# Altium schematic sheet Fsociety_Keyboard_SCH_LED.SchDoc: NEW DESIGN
size A1; CompanyName: Rena Electronica; Engineer: IK; Organization: Rena Electronica; Address1: de Ambachten 12; Address2: 4881 XZ; Address3: Zundert; Address4: the Netherlands; DocumentNumber: 05.xxx; Revision: 0.10; Customer: Klantnaam; PageSetup: Record=PageOptions¦CenterHorizontal=True¦CenterVertical=True¦PrintScale=0.52¦XCorrection=1.00¦YCorrection=1.00¦PrintKind=0¦BorderSize=5000000¦LeftOffset=0¦BottomOffset=0¦Orientation=2¦PaperLength=1000¦PaperWidth=1000¦Scale=100¦PaperSource=7¦PrintQuality=-3¦MediaType=1¦DitherType=10¦PrintScaleMode=1¦PaperKind=A3¦PaperIndex=8
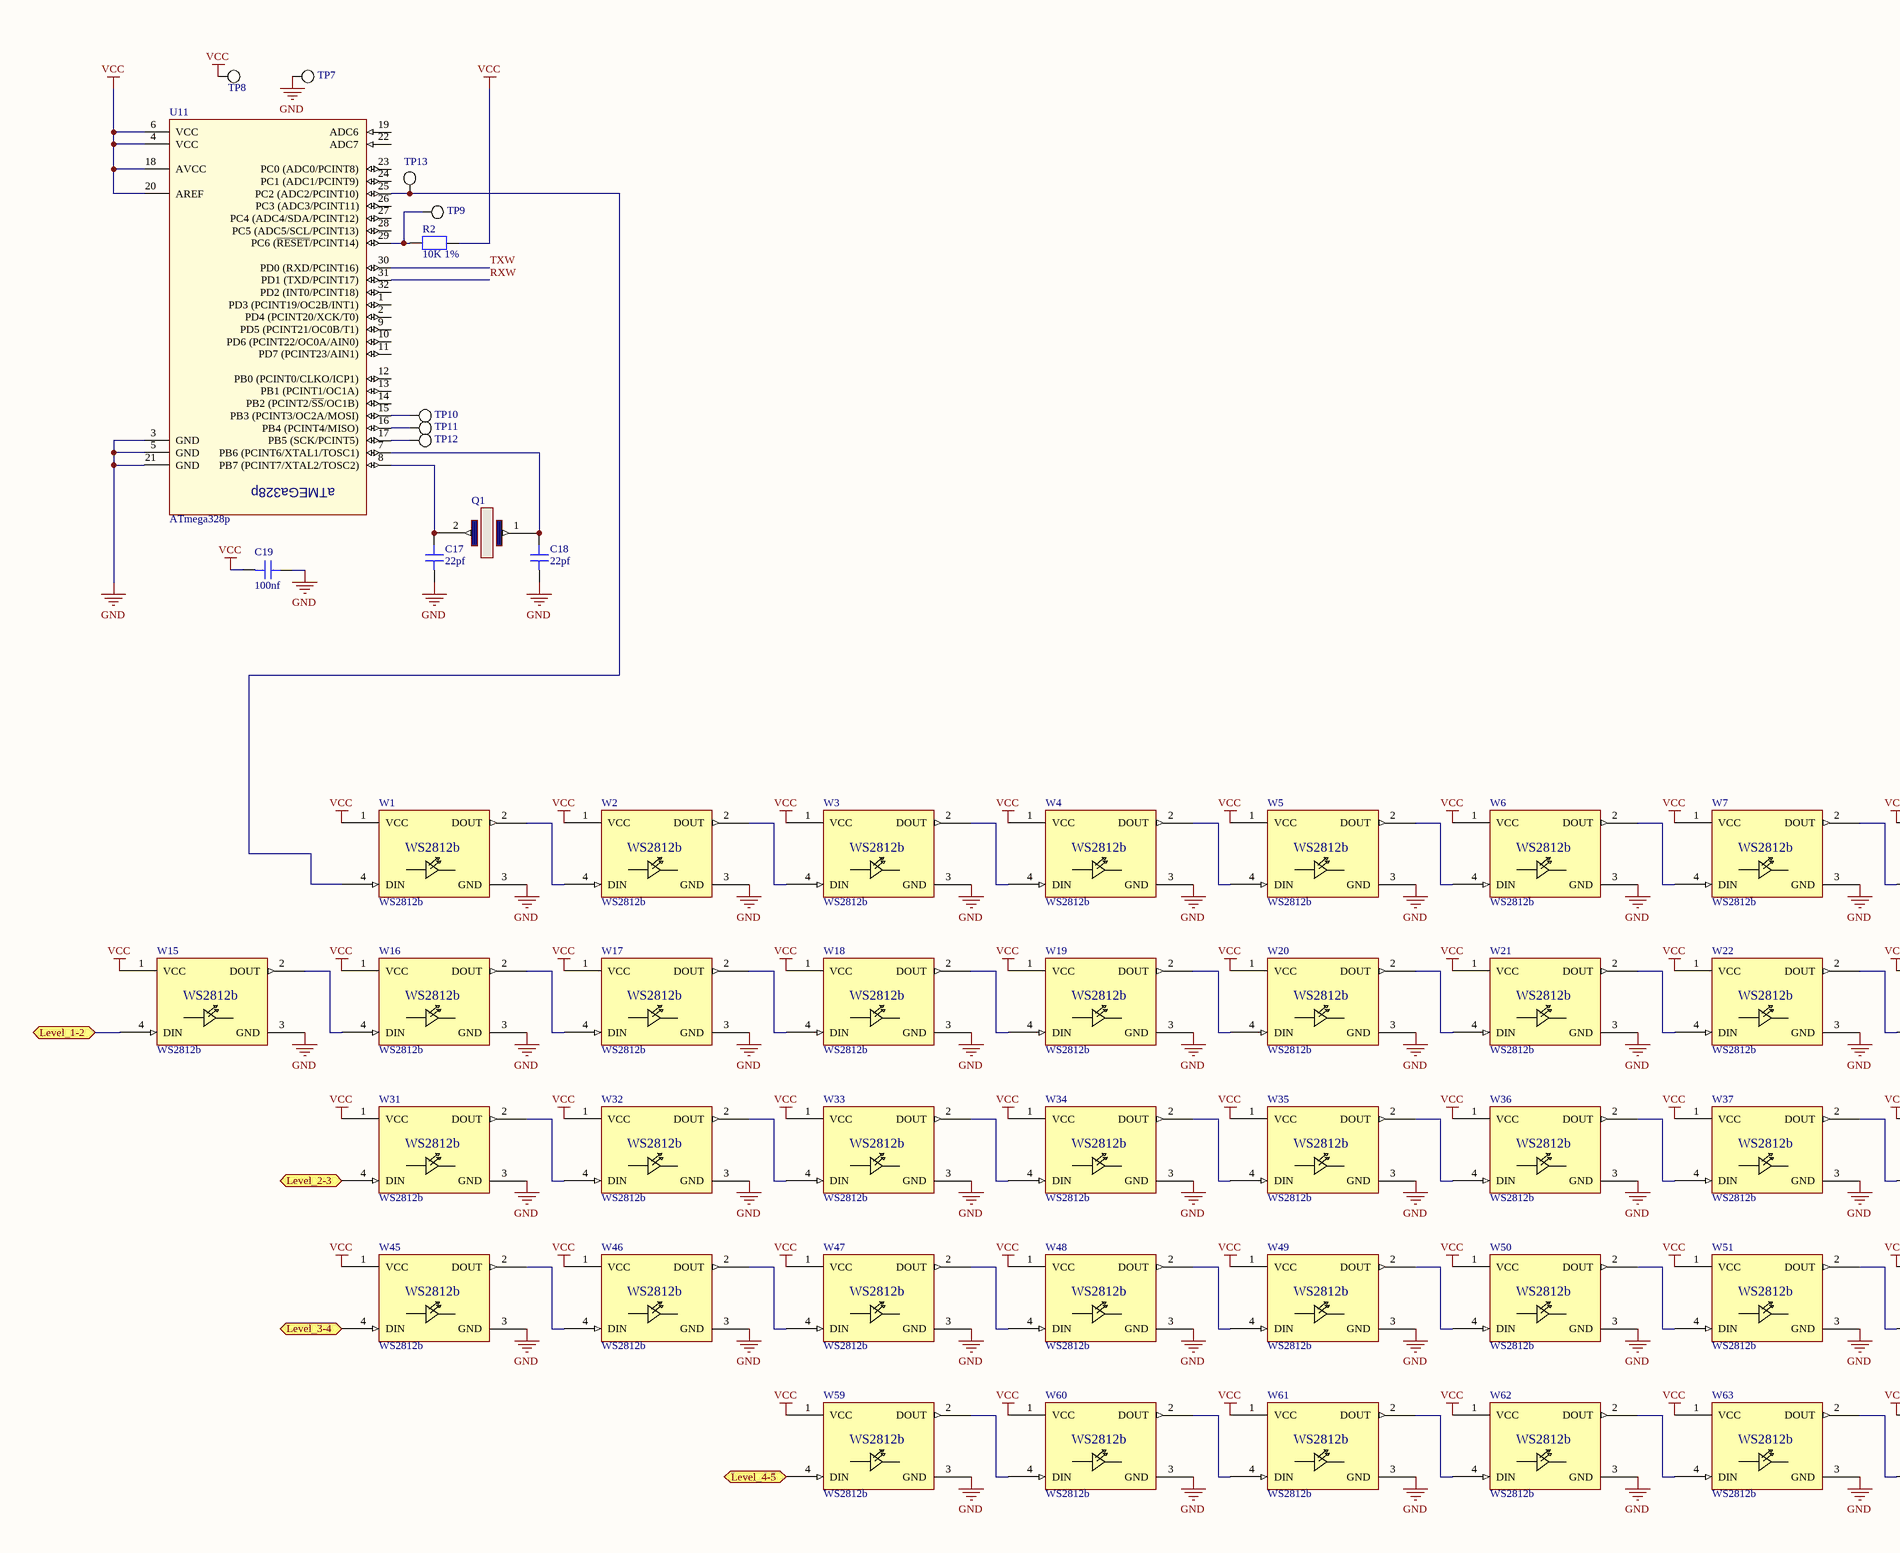
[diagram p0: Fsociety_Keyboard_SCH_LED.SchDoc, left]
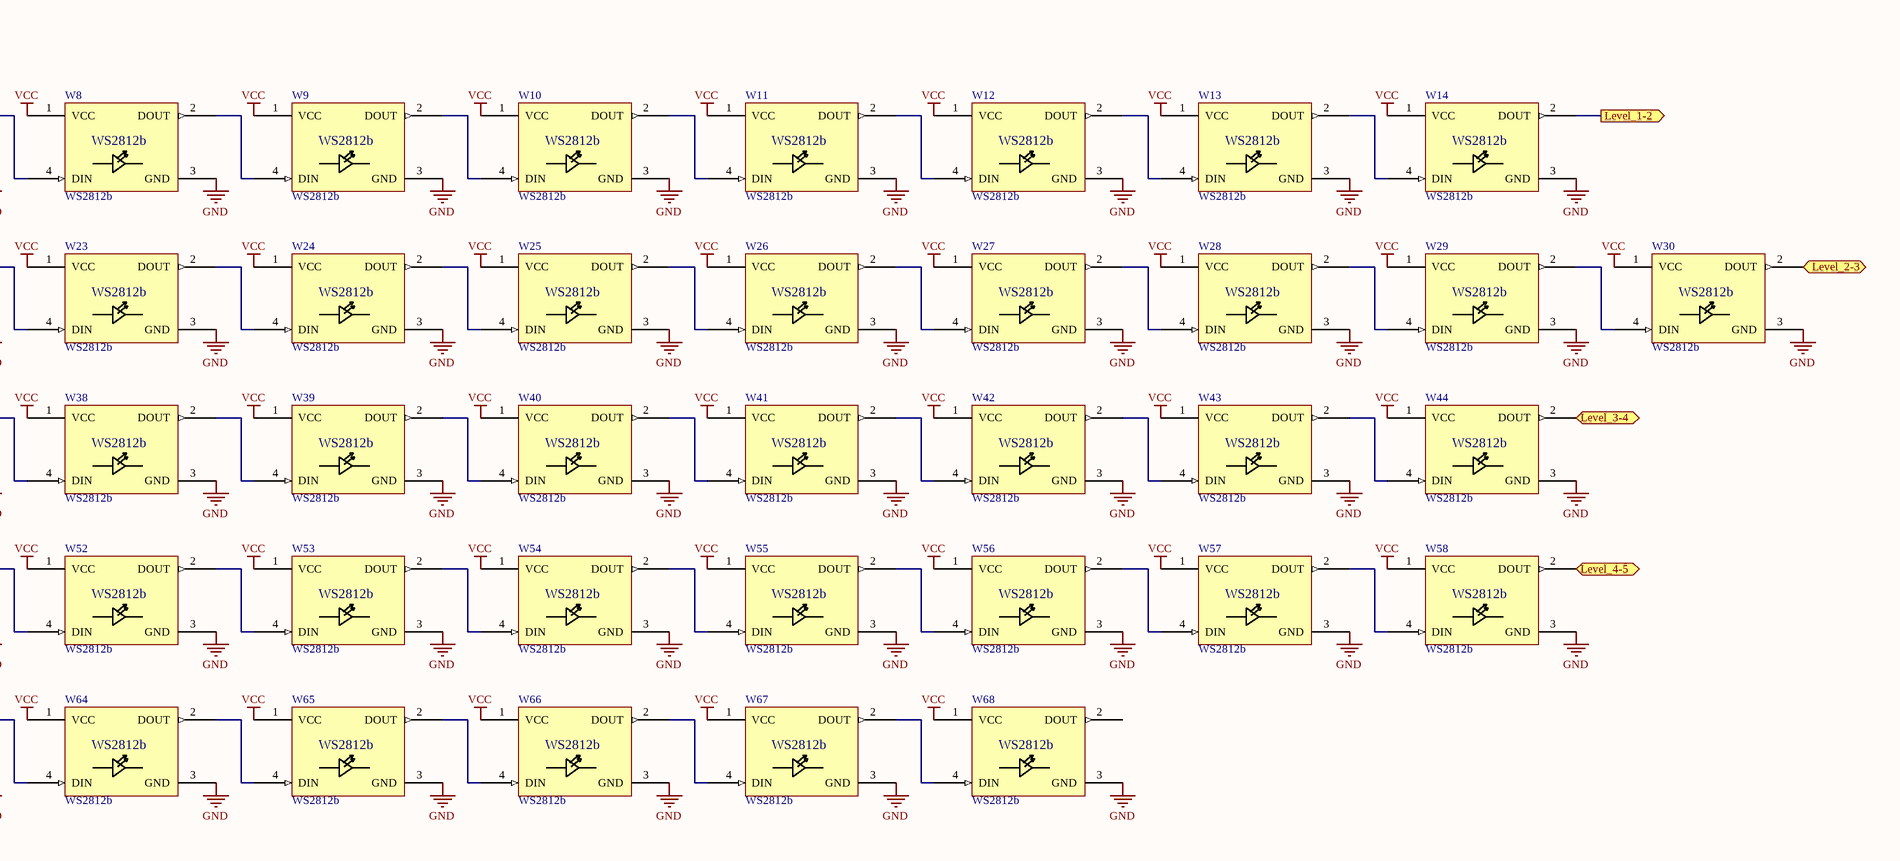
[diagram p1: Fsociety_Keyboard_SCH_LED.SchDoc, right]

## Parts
C17  22pf  [CAPC1608X08_NR]
C18  22pf  [CAPC1608X08_NR]
C19  100nf  [CAPC1608X08_NR]
Q1  Crystal_txc_sumasta  [Crystal_txc_sumasta]  (value not drawn)
R2  10K 1%  [RESC1608X06_NR]
TP7  TP  [TESTPAD-2MM]  (value not drawn)  (no BOM)
TP8  TP  [TESTPAD-2MM]  (value not drawn)  (no BOM)
TP9  TP  [TESTPAD-2MM]  (value not drawn)  (no BOM)
TP10  TP  [TESTPAD-2MM]  (value not drawn)  (no BOM)
TP11  TP  [TESTPAD-2MM]  (value not drawn)  (no BOM)
TP12  TP  [TESTPAD-2MM]  (value not drawn)  (no BOM)
TP13  TP  [TESTPAD-2MM]  (value not drawn)  (no BOM)
U11  ATmega328p  [TQFP32]
W1  WS2812b  [DIOC500500X250_NR]
W2  WS2812b  [DIOC500500X250_NR]
W3  WS2812b  [DIOC500500X250_NR]
W4  WS2812b  [DIOC500500X250_NR]
W5  WS2812b  [DIOC500500X250_NR]
W6  WS2812b  [DIOC500500X250_NR]
W7  WS2812b  [DIOC500500X250_NR]
W8  WS2812b  [DIOC500500X250_NR]
W9  WS2812b  [DIOC500500X250_NR]
W10  WS2812b  [DIOC500500X250_NR]
W11  WS2812b  [DIOC500500X250_NR]
W12  WS2812b  [DIOC500500X250_NR]
W13  WS2812b  [DIOC500500X250_NR]
W14  WS2812b  [DIOC500500X250_NR]
W15  WS2812b  [DIOC500500X250_NR]
W16  WS2812b  [DIOC500500X250_NR]
W17  WS2812b  [DIOC500500X250_NR]
W18  WS2812b  [DIOC500500X250_NR]
W19  WS2812b  [DIOC500500X250_NR]
W20  WS2812b  [DIOC500500X250_NR]
W21  WS2812b  [DIOC500500X250_NR]
W22  WS2812b  [DIOC500500X250_NR]
W23  WS2812b  [DIOC500500X250_NR]
W24  WS2812b  [DIOC500500X250_NR]
W25  WS2812b  [DIOC500500X250_NR]
W26  WS2812b  [DIOC500500X250_NR]
W27  WS2812b  [DIOC500500X250_NR]
W28  WS2812b  [DIOC500500X250_NR]
W29  WS2812b  [DIOC500500X250_NR]
W30  WS2812b  [DIOC500500X250_NR]
W31  WS2812b  [DIOC500500X250_NR]
W32  WS2812b  [DIOC500500X250_NR]
W33  WS2812b  [DIOC500500X250_NR]
W34  WS2812b  [DIOC500500X250_NR]
W35  WS2812b  [DIOC500500X250_NR]
W36  WS2812b  [DIOC500500X250_NR]
W37  WS2812b  [DIOC500500X250_NR]
W38  WS2812b  [DIOC500500X250_NR]
W39  WS2812b  [DIOC500500X250_NR]
W40  WS2812b  [DIOC500500X250_NR]
W41  WS2812b  [DIOC500500X250_NR]
W42  WS2812b  [DIOC500500X250_NR]
W43  WS2812b  [DIOC500500X250_NR]
W44  WS2812b  [DIOC500500X250_NR]
W45  WS2812b  [DIOC500500X250_NR]
W46  WS2812b  [DIOC500500X250_NR]
W47  WS2812b  [DIOC500500X250_NR]
W48  WS2812b  [DIOC500500X250_NR]
W49  WS2812b  [DIOC500500X250_NR]
W50  WS2812b  [DIOC500500X250_NR]
W51  WS2812b  [DIOC500500X250_NR]
W52  WS2812b  [DIOC500500X250_NR]
W53  WS2812b  [DIOC500500X250_NR]
W54  WS2812b  [DIOC500500X250_NR]
W55  WS2812b  [DIOC500500X250_NR]
W56  WS2812b  [DIOC500500X250_NR]
W57  WS2812b  [DIOC500500X250_NR]
W58  WS2812b  [DIOC500500X250_NR]
W59  WS2812b  [DIOC500500X250_NR]
W60  WS2812b  [DIOC500500X250_NR]
W61  WS2812b  [DIOC500500X250_NR]
W62  WS2812b  [DIOC500500X250_NR]
W63  WS2812b  [DIOC500500X250_NR]
W64  WS2812b  [DIOC500500X250_NR]
W65  WS2812b  [DIOC500500X250_NR]
W66  WS2812b  [DIOC500500X250_NR]
W67  WS2812b  [DIOC500500X250_NR]
W68  WS2812b  [DIOC500500X250_NR]

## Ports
Level_1-2, Level_1-2 (out), Level_2-3, Level_3-4, Level_4-5

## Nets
GND: C17.1 C18.1 C19.2 TP7.1 U11.3(GND) U11.5(GND) U11.21(GND) W1.3(GND) W2.3(GND) W3.3(GND) W4.3(GND) W5.3(GND) W6.3(GND) W7.3(GND) W8.3(GND) W9.3(GND) W10.3(GND) W11.3(GND) W12.3(GND) W13.3(GND) W14.3(GND) W15.3(GND) W16.3(GND) W17.3(GND) W18.3(GND) W19.3(GND) W20.3(GND) W21.3(GND) W22.3(GND) W23.3(GND) W24.3(GND) W25.3(GND) W26.3(GND) W27.3(GND) W28.3(GND) W29.3(GND) W30.3(GND) W31.3(GND) W32.3(GND) W33.3(GND) W34.3(GND) W35.3(GND) W36.3(GND) W37.3(GND) W38.3(GND) W39.3(GND) W40.3(GND) W41.3(GND) W42.3(GND) W43.3(GND) W44.3(GND) W45.3(GND) W46.3(GND) W47.3(GND) W48.3(GND) W49.3(GND) W50.3(GND) W51.3(GND) W52.3(GND) W53.3(GND) W54.3(GND) W55.3(GND) W56.3(GND) W57.3(GND) W58.3(GND) W59.3(GND) W60.3(GND) W61.3(GND) W62.3(GND) W63.3(GND) W64.3(GND) W65.3(GND) W66.3(GND) W67.3(GND) W68.3(GND)
VCC: C19.1 R2.1 TP8.1 U11.4(VCC) U11.6(VCC) U11.18(AVCC) U11.20(AREF) W1.1(VCC) W2.1(VCC) W3.1(VCC) W4.1(VCC) W5.1(VCC) W6.1(VCC) W7.1(VCC) W8.1(VCC) W9.1(VCC) W10.1(VCC) W11.1(VCC) W12.1(VCC) W13.1(VCC) W14.1(VCC) W15.1(VCC) W16.1(VCC) W17.1(VCC) W18.1(VCC) W19.1(VCC) W20.1(VCC) W21.1(VCC) W22.1(VCC) W23.1(VCC) W24.1(VCC) W25.1(VCC) W26.1(VCC) W27.1(VCC) W28.1(VCC) W29.1(VCC) W30.1(VCC) W31.1(VCC) W32.1(VCC) W33.1(VCC) W34.1(VCC) W35.1(VCC) W36.1(VCC) W37.1(VCC) W38.1(VCC) W39.1(VCC) W40.1(VCC) W41.1(VCC) W42.1(VCC) W43.1(VCC) W44.1(VCC) W45.1(VCC) W46.1(VCC) W47.1(VCC) W48.1(VCC) W49.1(VCC) W50.1(VCC) W51.1(VCC) W52.1(VCC) W53.1(VCC) W54.1(VCC) W55.1(VCC) W56.1(VCC) W57.1(VCC) W58.1(VCC) W59.1(VCC) W60.1(VCC) W61.1(VCC) W62.1(VCC) W63.1(VCC) W64.1(VCC) W65.1(VCC) W66.1(VCC) W67.1(VCC) W68.1(VCC)
Level_1-2: W14.2(DOUT) W15.4(DIN) ; port Level_1-2
Level_2-3: W30.2(DOUT) W31.4(DIN) ; port Level_2-3
Level_3-4: W44.2(DOUT) W45.4(DIN) ; port Level_3-4
Level_4-5: W58.2(DOUT) W59.4(DIN) ; port Level_4-5
RXW: U11.31(PD1_(TXD/PCINT17))
TXW: U11.30(PD0_(RXD/PCINT16))
NetC17_2: C17.2 Q1.2 U11.8(PB7_(PCINT7/XTAL2/TOSC2))
NetC18_2: C18.2 Q1.1 U11.7(PB6_(PCINT6/XTAL1/TOSC1))
NetR2_2: R2.2 TP9.1 U11.29(PC6_(~{RESET}/PCINT14))
NetTP10_1: TP10.1 U11.15(PB3_(PCINT3/OC2A/MOSI))
NetTP11_1: TP11.1 U11.16(PB4_(PCINT4/MISO))
NetTP12_1: TP12.1 U11.17(PB5_(SCK/PCINT5))
NetTP13_1: TP13.1 U11.25(PC2_(ADC2/PCINT10)) W1.4(DIN)
NetW1_2: W1.2(DOUT) W2.4(DIN)
NetW2_2: W2.2(DOUT) W3.4(DIN)
NetW3_2: W3.2(DOUT) W4.4(DIN)
NetW4_2: W4.2(DOUT) W5.4(DIN)
NetW5_2: W5.2(DOUT) W6.4(DIN)
NetW6_2: W6.2(DOUT) W7.4(DIN)
NetW7_2: W7.2(DOUT) W8.4(DIN)
NetW8_2: W8.2(DOUT) W9.4(DIN)
NetW9_2: W9.2(DOUT) W10.4(DIN)
NetW10_2: W10.2(DOUT) W11.4(DIN)
NetW11_2: W11.2(DOUT) W12.4(DIN)
NetW12_2: W12.2(DOUT) W13.4(DIN)
NetW13_2: W13.2(DOUT) W14.4(DIN)
NetW15_2: W15.2(DOUT) W16.4(DIN)
NetW16_2: W16.2(DOUT) W17.4(DIN)
NetW17_2: W17.2(DOUT) W18.4(DIN)
NetW18_2: W18.2(DOUT) W19.4(DIN)
NetW19_2: W19.2(DOUT) W20.4(DIN)
NetW20_2: W20.2(DOUT) W21.4(DIN)
NetW21_2: W21.2(DOUT) W22.4(DIN)
NetW22_2: W22.2(DOUT) W23.4(DIN)
NetW23_2: W23.2(DOUT) W24.4(DIN)
NetW24_2: W24.2(DOUT) W25.4(DIN)
NetW25_2: W25.2(DOUT) W26.4(DIN)
NetW26_2: W26.2(DOUT) W27.4(DIN)
NetW27_2: W27.2(DOUT) W28.4(DIN)
NetW28_2: W28.2(DOUT) W29.4(DIN)
NetW29_2: W29.2(DOUT) W30.4(DIN)
NetW31_2: W31.2(DOUT) W32.4(DIN)
NetW32_2: W32.2(DOUT) W33.4(DIN)
NetW33_2: W33.2(DOUT) W34.4(DIN)
NetW34_2: W34.2(DOUT) W35.4(DIN)
NetW35_2: W35.2(DOUT) W36.4(DIN)
NetW36_2: W36.2(DOUT) W37.4(DIN)
NetW37_2: W37.2(DOUT) W38.4(DIN)
NetW38_2: W38.2(DOUT) W39.4(DIN)
NetW39_2: W39.2(DOUT) W40.4(DIN)
NetW40_2: W40.2(DOUT) W41.4(DIN)
NetW41_2: W41.2(DOUT) W42.4(DIN)
NetW42_2: W42.2(DOUT) W43.4(DIN)
NetW43_2: W43.2(DOUT) W44.4(DIN)
NetW45_2: W45.2(DOUT) W46.4(DIN)
NetW46_2: W46.2(DOUT) W47.4(DIN)
NetW47_2: W47.2(DOUT) W48.4(DIN)
NetW48_2: W48.2(DOUT) W49.4(DIN)
NetW49_2: W49.2(DOUT) W50.4(DIN)
NetW50_2: W50.2(DOUT) W51.4(DIN)
NetW51_2: W51.2(DOUT) W52.4(DIN)
NetW52_2: W52.2(DOUT) W53.4(DIN)
NetW53_2: W53.2(DOUT) W54.4(DIN)
NetW54_2: W54.2(DOUT) W55.4(DIN)
NetW55_2: W55.2(DOUT) W56.4(DIN)
NetW56_2: W56.2(DOUT) W57.4(DIN)
NetW57_2: W57.2(DOUT) W58.4(DIN)
NetW59_2: W59.2(DOUT) W60.4(DIN)
NetW60_2: W60.2(DOUT) W61.4(DIN)
NetW61_2: W61.2(DOUT) W62.4(DIN)
NetW62_2: W62.2(DOUT) W63.4(DIN)
NetW63_2: W63.2(DOUT) W64.4(DIN)
NetW64_2: W64.2(DOUT) W65.4(DIN)
NetW65_2: W65.2(DOUT) W66.4(DIN)
NetW66_2: W66.2(DOUT) W67.4(DIN)
NetW67_2: W67.2(DOUT) W68.4(DIN)

Not connected (* = marked no-connect by the designer): U11 1(PD3_(PCINT19/OC2B/INT1)) 2(PD4_(PCINT20/XCK/T0)) 9(PD5_(PCINT21/OC0B/T1)) 10(PD6_(PCINT22/OC0A/AIN0)) 11(PD7_(PCINT23/AIN1)) 12(PB0_(PCINT0/CLKO/ICP1)) 13(PB1_(PCINT1/OC1A)) 14(PB2_(PCINT2/~{SS}/OC1B)) 19(ADC6) 22(ADC7) 23(PC0_(ADC0/PCINT8)) 24(PC1_(ADC1/PCINT9)) 26(PC3_(ADC3/PCINT11)) 27(PC4_(ADC4/SDA/PCINT12)) 28(PC5_(ADC5/SCL/PCINT13)) 32(PD2_(INT0/PCINT18)); W68 2(DOUT)

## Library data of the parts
C17-C19 = CMP-00064-A.5: Capacitor 10nF X7R ±10% 50V 0603(1608) SMD; MAXPartNumber: 10N/50-0603!; Case-EIA: 0603; Case-Metric: 1608
R2 = CMP-00060-A.4: 10K  0.1W 1% 0603(1608 Metric) SMD; MaxPartNumber: 10K-0603!; Case-EIA: 0603; Case-Metric: 1608; Value: 10K Ohm
TP7-TP13 = CMP-00759-A.11: TESTPOINT; FLS_PN: TP#
W1-W68 = WS2812b_Sumasta: The Infamous Chinese Chainable RGB LED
